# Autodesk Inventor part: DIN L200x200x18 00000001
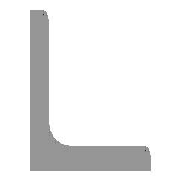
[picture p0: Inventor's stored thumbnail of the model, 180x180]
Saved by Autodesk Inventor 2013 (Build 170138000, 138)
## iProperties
_CCFamilyMember: 400
_CCFamilyDisplayName: DIN EN 10056-1 (Hot-rolled structural steel section-Equal angles) - Hot-rolled structural steel section-Equal angles
_FrameMemberDoc: Frame Member File
_Version: 15.0.0
Created: 2009-11
Part Number: DIN L200x200x18 00000001
Material: Steel, Mild
Description: Hot-rolled structural steel section-Equal angles
Document SubType Name: Modeling
Standard: DIN
Designer: pokornp
Standard Revision: 1998
Standards Organization: DIN
Language: en-US
Size Designation: L200x200x18
Categories: <MemberInstance><Categories><Category DisplayName="Structural Shapes" InternalName="089c4875-fa83-4c05-b084-43b9cc11f5ed" Mnemonic="GRDR"><CategoryParameter Dis
Stock Number: L200x200x18
Density: 7.86 g/cm^3
Mass: 106464 g
Surface Area: 15515.4 cm^2
Volume: 13545.1 cm^3
IsCustomPart: 1
G_L: 1960.000 mm
G_W: 200.000 mm
G_H: 200.000 mm
Author: pokornp
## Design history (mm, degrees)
node "Start plane"
node "End plane"
sketch "Sketch"
  geometry: L1 (-37.533, -19.533)-(-37.533, 135.467); L2 (-55.533, 144.467)-(-46.533, 144.467); L3 (-55.533, -55.533)-(-55.533, 144.467); L4 (-55.533, -55.533)-(144.467, -55.533); L5 (144.467, -46.533)-(144.467, -55.533); L6 (-19.533, -37.533)-(135.467, -37.533); L7 (0, 186.703)-(0, -95.906) reference; L8 (-95.906, 0)-(186.703, 0) reference; A1 r 18 centre (-19.533, -19.533) between (-37.533, -19.533) and (-19.533, -37.533); A2 r 9 centre (-46.533, 135.467) between (-37.533, 135.467) and (-46.533, 144.467); A3 r 9 centre (135.467, -46.533) between (144.467, -46.533) and (135.467, -37.533); 3 further points
  constraints: 12 end point, 6 point on circle, 6 point on line, 6 tangent, 3 centre point, 3 horizontal, 3 vertical, 1 equal radius
  dimensions: "d4" = 200 distance of L3.start L4.end (= b); "d6" = 200 distance of L3.start L2.start (= b); "d8" = 18 distance of point (144.467, -37.533) L4.end (= ParT); "d10" = 18 distance of L2.start point (-37.533, 144.467) (= ParT); "d17" = 18 radius of A1 (= R); "d18" = 9 radius of A2 (= R1); "d19" = 55.53331 distance between parallel lines of L8 L4 (= ex); "d20" = 55.53331 distance between parallel lines of L3 L7 (= d19)
extrude "Body" new body sketch "Sketch" stored distance "d11" = 1960 (= G_L); taper "d12" = 0 deg
node "Driven Length"
  sketch "Sketch3"
    geometry: L1 (0, 0)-(10, 0) reference
    constraints: 2 end point, 1 horizontal
  workplane "Work Plane10"
  sketch "Sketch4"
    geometry: L1 (-2, 0)-(12, 0) reference; L2 (-2, 1960)-(12, 1960) reference
    dimensions: "d24" = 1960 distance between parallel lines of L1 L2 (derived)
body "Solid1"
other parameters: "b" = 200 [user parameter; used in 3 equation terms], "ParT" = 18 [user parameter; used in 3 equation terms], "R" = 18 [user parameter; used in 1 equation term], "R1" = 9 [user parameter; used in 1 equation term], "G_L" = 1960 (= d24) [user parameter; used in 1 equation term], "d7" = 4 (derived), "d9" = 4 (derived), "ex" = 55.53331 (computed from b, ParT) [user parameter; used in 1 equation term], "G_OFFSET_START" = 0 [user parameter; used in 1 equation term], "G_OFFSET_END" = 0 [user parameter; used in 1 equation term], "d21" = 0 (computed from G_OFFSET_START), "d23" = 90 deg
